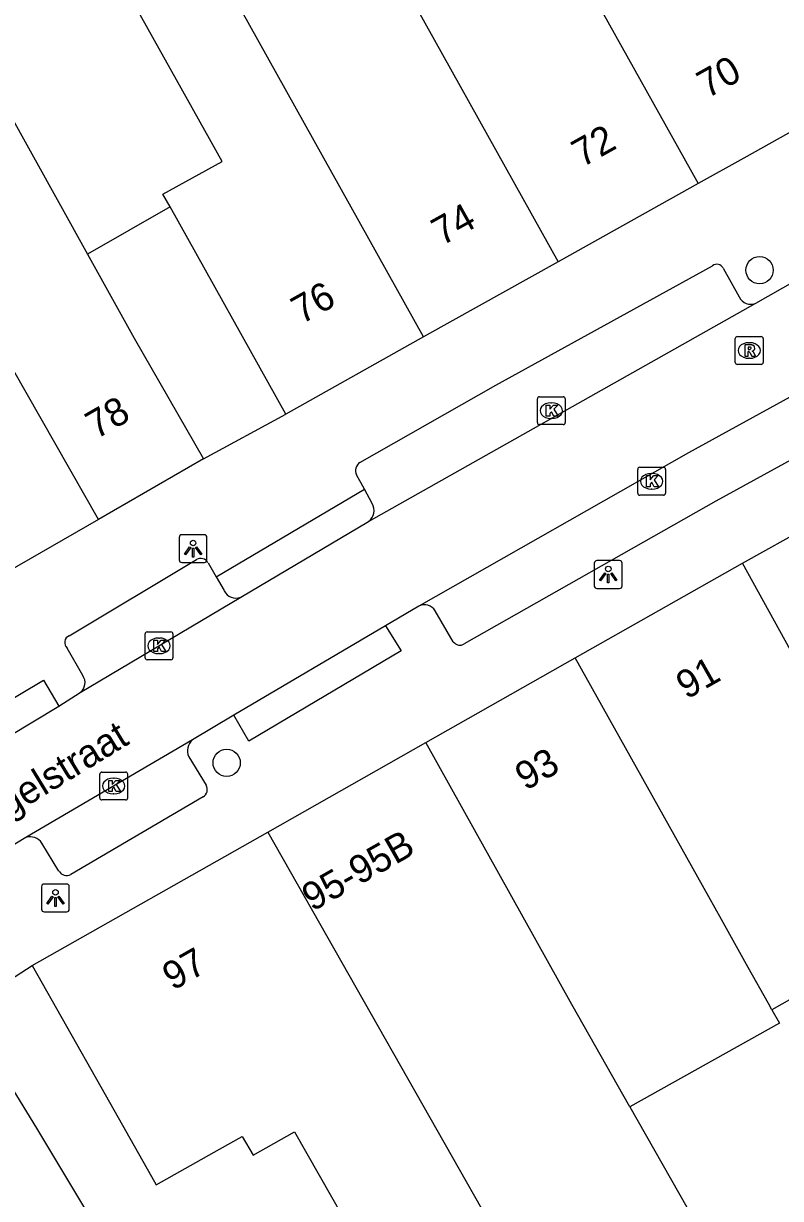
# Model space of a CAD drawing. Extents: x 159718 to 160783, y 383290 to 384030.
# Drawn here: x 160474.17 to 160501.32, y 383362.07 to 383404.19 of the extents above; entities that cross this region are included whole.
import ezdxf

# ---------------------------------------------------------------- set-up
doc = ezdxf.new("R2010")
doc.units = 0
for name, color, linetype in [('IMGEO_Boom', 7, 'Continuous'), ('IMGEO_Kolk', 7, 'Continuous'), ('IMGEO_Lichtpunt', 7, 'Continuous'), ('IMGEO_Openbare_ruimte_label', 7, 'Continuous'), ('IMGEO_Pand', 7, 'Continuous'), ('IMGEO_Pand_nummerreeks', 7, 'Continuous'), ('IMGEO_Pand_overbouw', 7, 'Continuous'), ('IMGEO_Rijbaan_lokaal_open', 7, 'Continuous'), ('IMGEO_Rioolput', 7, 'Continuous'), ('IMGEO_Voetpad_open', 7, 'Continuous')]:
    doc.layers.add(name, color=color, linetype=linetype)

msp = doc.modelspace()

# ---------------------------------------------------------------- linework, layer by layer
at = {"layer": 'IMGEO_Boom'}
for centre in [(160500.57, 383395.347), (160481.459, 383377.686)]:
    msp.add_circle(centre, 0.489, dxfattribs=at)
at = {"layer": 'IMGEO_Kolk'}
for p, q in [((160492.6, 383389.884), (160492.6, 383390.736)), ((160492.675, 383390.81), (160493.527, 383390.81)), ((160493.601, 383390.736), (160493.601, 383389.884)), ((160493.088, 383390.59), (160493.113, 383390.59)), ((160493.527, 383389.81), (160492.675, 383389.81)), ((160493.111, 383390.03), (160493.086, 383390.03)), ((160496.197, 383387.355), (160496.197, 383388.207)), ((160496.272, 383388.281), (160497.124, 383388.281)), ((160497.198, 383388.207), (160497.198, 383387.355)), ((160496.685, 383388.061), (160496.71, 383388.061)), ((160497.124, 383387.281), (160496.272, 383387.281)), ((160496.708, 383387.501), (160496.683, 383387.501)), ((160478.532, 383381.454), (160478.532, 383382.306)), ((160478.607, 383382.38), (160479.459, 383382.38)), ((160479.533, 383382.306), (160479.533, 383381.454)), ((160479.02, 383382.16), (160479.045, 383382.16)), ((160479.459, 383381.38), (160478.607, 383381.38)), ((160479.043, 383381.6), (160479.018, 383381.6)), ((160476.908, 383376.428), (160476.908, 383377.28)), ((160476.983, 383377.354), (160477.835, 383377.354)), ((160477.396, 383377.134), (160477.421, 383377.134)), ((160477.909, 383377.28), (160477.909, 383376.428)), ((160477.835, 383376.354), (160476.983, 383376.354)), ((160477.419, 383376.574), (160477.394, 383376.574))]:
    msp.add_line(p, q, dxfattribs=at)
for points in [[(160492.6, 383389.884), (160492.6, 383390.736)], [(160492.675, 383390.81), (160493.527, 383390.81)], [(160493.601, 383390.736), (160493.601, 383389.884)], [(160492.921, 383390.51), (160493.044, 383390.51), (160493.044, 383390.359), (160493.174, 383390.51), (160493.338, 383390.51), (160493.192, 383390.359), (160493.345, 383390.11), (160493.193, 383390.11), (160493.108, 383390.274), (160493.044, 383390.207), (160493.044, 383390.11), (160492.921, 383390.11), (160492.921, 383390.51)], [(160493.527, 383389.81), (160492.675, 383389.81)], [(160496.197, 383387.355), (160496.197, 383388.207)], [(160496.272, 383388.281), (160497.124, 383388.281)], [(160497.198, 383388.207), (160497.198, 383387.355)], [(160496.518, 383387.981), (160496.641, 383387.981), (160496.641, 383387.83), (160496.771, 383387.981), (160496.935, 383387.981), (160496.789, 383387.83), (160496.942, 383387.581), (160496.79, 383387.581), (160496.705, 383387.745), (160496.641, 383387.678), (160496.641, 383387.581), (160496.518, 383387.581), (160496.518, 383387.981)], [(160497.124, 383387.281), (160496.272, 383387.281)], [(160478.532, 383381.454), (160478.532, 383382.306)], [(160478.607, 383382.38), (160479.459, 383382.38)], [(160479.533, 383382.306), (160479.533, 383381.454)], [(160478.853, 383382.08), (160478.976, 383382.08), (160478.976, 383381.929), (160479.106, 383382.08), (160479.27, 383382.08), (160479.124, 383381.929), (160479.277, 383381.68), (160479.125, 383381.68), (160479.04, 383381.844), (160478.976, 383381.777), (160478.976, 383381.68), (160478.853, 383381.68), (160478.853, 383382.08)], [(160479.459, 383381.38), (160478.607, 383381.38)], [(160476.908, 383376.428), (160476.908, 383377.28)], [(160476.983, 383377.354), (160477.835, 383377.354)], [(160477.909, 383377.28), (160477.909, 383376.428)], [(160477.229, 383377.054), (160477.352, 383377.054), (160477.352, 383376.903), (160477.482, 383377.054), (160477.646, 383377.054), (160477.5, 383376.903), (160477.653, 383376.654), (160477.501, 383376.654), (160477.416, 383376.818), (160477.352, 383376.751), (160477.352, 383376.654), (160477.229, 383376.654), (160477.229, 383377.054)], [(160477.835, 383376.354), (160476.983, 383376.354)]]:
    msp.add_lwpolyline(points, dxfattribs=at)
for centre, start, end in [((160492.677, 383390.734), 91.552, 178.448), ((160492.677, 383390.734), 91.552, 178.448), ((160493.525, 383390.734), 1.552, 88.448), ((160493.525, 383390.734), 1.552, 88.448), ((160492.677, 383389.886), 181.552, 268.448), ((160492.677, 383389.886), 181.552, 268.448), ((160493.525, 383389.886), 271.552, 358.448), ((160493.525, 383389.886), 271.552, 358.448), ((160496.274, 383388.205), 91.552, 178.448), ((160496.274, 383388.205), 91.552, 178.448), ((160497.122, 383388.205), 1.552, 88.448), ((160497.122, 383388.205), 1.552, 88.448), ((160496.274, 383387.357), 181.552, 268.448), ((160496.274, 383387.357), 181.552, 268.448), ((160497.122, 383387.357), 271.552, 358.448), ((160497.122, 383387.357), 271.552, 358.448), ((160478.609, 383382.304), 91.552, 178.448), ((160478.609, 383382.304), 91.552, 178.448), ((160479.457, 383382.304), 1.552, 88.448), ((160479.457, 383382.304), 1.552, 88.448), ((160478.609, 383381.456), 181.552, 268.448), ((160478.609, 383381.456), 181.552, 268.448), ((160479.457, 383381.456), 271.552, 358.448), ((160479.457, 383381.456), 271.552, 358.448), ((160476.985, 383377.278), 91.552, 178.448), ((160476.985, 383377.278), 91.552, 178.448), ((160477.833, 383377.278), 1.552, 88.448), ((160477.833, 383377.278), 1.552, 88.448), ((160476.985, 383376.43), 181.552, 268.448), ((160476.985, 383376.43), 181.552, 268.448), ((160477.833, 383376.43), 271.552, 358.448), ((160477.833, 383376.43), 271.552, 358.448)]:
    msp.add_arc(centre, 0.0765, start, end, dxfattribs=at)
for centre, major_axis, ratio, start_param, end_param in [((160493.087, 383390.31), (-0.387, 0.002), 0.722429, 4.712389, 7.853982), ((160493.112, 383390.31), (-0.39, 0.002), 0.717154, 1.570796, 4.712389), ((160496.684, 383387.781), (-0.387, 0.002), 0.722429, 4.712389, 7.853982), ((160496.709, 383387.781), (-0.39, 0.002), 0.717154, 1.570796, 4.712389), ((160479.019, 383381.88), (-0.387, 0.002), 0.722429, 4.712389, 7.853982), ((160479.044, 383381.88), (-0.39, 0.002), 0.717154, 1.570796, 4.712389), ((160477.395, 383376.854), (-0.387, 0.002), 0.722429, 4.712389, 7.853982), ((160477.42, 383376.854), (-0.39, 0.002), 0.717154, 1.570796, 4.712389)]:
    msp.add_ellipse(centre, major_axis=major_axis, ratio=ratio, start_param=start_param, end_param=end_param, dxfattribs=at)
at = {"layer": 'IMGEO_Lichtpunt'}
for p, q in [((160479.757, 383385.768), (160479.757, 383384.961)), ((160479.757, 383385.768), (160479.757, 383384.961)), ((160480.659, 383385.863), (160479.851, 383385.863)), ((160480.659, 383385.863), (160479.851, 383385.863)), ((160480.753, 383384.961), (160480.753, 383385.768)), ((160480.753, 383384.961), (160480.753, 383385.768)), ((160479.851, 383384.867), (160480.659, 383384.867)), ((160479.851, 383384.867), (160480.659, 383384.867)), ((160494.643, 383384.839), (160494.643, 383384.032)), ((160494.643, 383384.839), (160494.643, 383384.032)), ((160495.545, 383384.934), (160494.737, 383384.934)), ((160495.545, 383384.934), (160494.737, 383384.934)), ((160495.639, 383384.032), (160495.639, 383384.839)), ((160495.639, 383384.032), (160495.639, 383384.839)), ((160494.737, 383383.938), (160495.545, 383383.938)), ((160494.737, 383383.938), (160495.545, 383383.938)), ((160475.723, 383373.34), (160474.915, 383373.34)), ((160475.723, 383373.34), (160474.915, 383373.34)), ((160474.821, 383373.245), (160474.821, 383372.438)), ((160474.821, 383373.245), (160474.821, 383372.438)), ((160475.817, 383372.438), (160475.817, 383373.245)), ((160475.817, 383372.438), (160475.817, 383373.245)), ((160474.915, 383372.344), (160475.723, 383372.344)), ((160474.915, 383372.344), (160475.723, 383372.344))]:
    msp.add_line(p, q, dxfattribs=at)
for points in [[(160480.131, 383385.432), (160480.17, 383385.404), (160479.982, 383385.142), (160479.944, 383385.169), (160480.131, 383385.432)], [(160480.233, 383385.384), (160480.28, 383385.384), (160480.28, 383385.062), (160480.233, 383385.062), (160480.233, 383385.384)], [(160480.343, 383385.404), (160480.381, 383385.431), (160480.568, 383385.169), (160480.529, 383385.141), (160480.343, 383385.404)], [(160495.017, 383384.503), (160495.056, 383384.475), (160494.868, 383384.213), (160494.83, 383384.24), (160495.017, 383384.503)], [(160495.119, 383384.455), (160495.166, 383384.455), (160495.166, 383384.133), (160495.119, 383384.133), (160495.119, 383384.455)], [(160495.229, 383384.475), (160495.267, 383384.502), (160495.454, 383384.24), (160495.415, 383384.212), (160495.229, 383384.475)], [(160475.195, 383372.909), (160475.234, 383372.881), (160475.046, 383372.619), (160475.008, 383372.646), (160475.195, 383372.909)], [(160475.407, 383372.881), (160475.445, 383372.908), (160475.632, 383372.646), (160475.593, 383372.618), (160475.407, 383372.881)], [(160475.297, 383372.861), (160475.344, 383372.861), (160475.344, 383372.539), (160475.297, 383372.539), (160475.297, 383372.861)]]:
    msp.add_lwpolyline(points, dxfattribs=at)
for centre in [(160480.256, 383385.566), (160495.142, 383384.637), (160475.32, 383373.043)]:
    msp.add_circle(centre, 0.0994, dxfattribs=at)
for centre, start, end in [((160479.851, 383385.768), 90, 180), ((160479.851, 383385.768), 90, 180), ((160480.659, 383385.768), 0, 90), ((160480.659, 383385.768), 0, 90), ((160479.851, 383384.961), 180, 270), ((160479.851, 383384.961), 180, 270), ((160480.659, 383384.961), 270, 0), ((160480.659, 383384.961), 270, 360), ((160494.737, 383384.839), 90, 180), ((160494.737, 383384.839), 90, 180), ((160495.545, 383384.839), 0, 90), ((160495.545, 383384.839), 0, 90), ((160494.737, 383384.032), 180, 270), ((160494.737, 383384.032), 180, 270), ((160495.545, 383384.032), 270, 0), ((160495.545, 383384.032), 270, 360), ((160474.915, 383373.245), 90, 180), ((160474.915, 383373.245), 90, 180), ((160475.723, 383373.245), 0, 90), ((160475.723, 383373.245), 0, 90), ((160474.915, 383372.438), 180, 270), ((160474.915, 383372.438), 180, 270), ((160475.723, 383372.438), 270, 0), ((160475.723, 383372.438), 270, 360)]:
    msp.add_arc(centre, 0.0946, start, end, dxfattribs=at)
at = {"layer": 'IMGEO_Pand'}
for points in [[(160483.576, 383390.191), (160479.428, 383397.615), (160479.174, 383398.069), (160481.294, 383399.245), (160476.163, 383408.441), (160479.001, 383410.024)], [(160488.523, 383392.955), (160479.001, 383410.024)], [(160491.733, 383410.343), (160492.53, 383408.915), (160493.994, 383406.29), (160498.365, 383398.454)], [(160486.659, 383407.637), (160493.351, 383395.653)], [(160468.633, 383400.841), (160470.138, 383401.679), (160472.525, 383403.008), (160476.473, 383395.916), (160478.141, 383392.915), (160480.633, 383388.58)], [(160503.208, 383401.16), (160500, 383399.368), (160498.365, 383398.454)], [(160476.865, 383386.414), (160468.633, 383400.841)], [(160498.365, 383398.454), (160493.351, 383395.653)], [(160493.351, 383395.653), (160488.523, 383392.955)], [(160488.523, 383392.955), (160483.576, 383390.191)], [(160499.951, 383384.846), (160502.36, 383386.185), (160502.304, 383386.297), (160508.086, 383389.549)], [(160480.633, 383388.58), (160476.865, 383386.414)], [(160476.865, 383386.414), (160469.81, 383382.357)], [(160493.953, 383381.448), (160499.951, 383384.846)], [(160506.411, 383371.894), (160505.555, 383373.403), (160506.097, 383373.71), (160505.947, 383373.998), (160499.951, 383384.846)], [(160488.601, 383378.414), (160493.953, 383381.448)], [(160501.011, 383368.832), (160500.886, 383369.055), (160500.164, 383370.345), (160499.197, 383372.073), (160498.744, 383372.883), (160493.953, 383381.448)], [(160482.934, 383375.203), (160488.601, 383378.414)], [(160495.919, 383365.354), (160493.834, 383369.027), (160488.601, 383378.414)], [(160474.49, 383370.418), (160482.934, 383375.203)], [(160482.934, 383375.203), (160491.645, 383359.858), (160492.727, 383357.952)], [(160506.411, 383371.894), (160501.011, 383368.832)], [(160474.49, 383370.418), (160476.949, 383366.065), (160478.765, 383362.85), (160478.932, 383362.554), (160481.205, 383363.833), (160482.02, 383364.291), (160482.405, 383363.614), (160483.893, 383364.459), (160486.934, 383359.106), (160486.44, 383358.826)], [(160472.243, 383354.191), (160478.604, 383358.023), (160476.988, 383360.706), (160474.653, 383364.584), (160472.034, 383368.843)], [(160501.011, 383368.832), (160501.279, 383368.353), (160495.919, 383365.354)], [(160495.919, 383365.354), (160500, 383358.164), (160500.229, 383357.761), (160500.597, 383357.113), (160504.871, 383359.614), (160506.61, 383356.155), (160506.076, 383351.936), (160510.595, 383351.363)]]:
    msp.add_lwpolyline(points, dxfattribs=at)
at = {"layer": 'IMGEO_Pand_overbouw'}
msp.add_lwpolyline([(160479.428, 383397.615), (160476.473, 383395.916), (160478.141, 383392.915), (160480.633, 383388.58), (160483.576, 383390.191)], close=True, dxfattribs=at)
at = {"layer": 'IMGEO_Rijbaan_lokaal_open'}
for points in [[(160509.795, 383395.27), (160498.016, 383388.805), (160488.35, 383383.3)], [(160500.433, 383394.16), (160501.848, 383394.965)], [(160486.541, 383386.343), (160500.433, 383394.16)], [(160481.968, 383383.62), (160486.541, 383386.343)], [(160476.209, 383380.206), (160481.968, 383383.62)], [(160488.35, 383383.3), (160487.16, 383382.594)], [(160487.16, 383382.594), (160481.715, 383379.396)], [(160475.436, 383379.714), (160476.209, 383380.206)], [(160471.815, 383377.547), (160475.436, 383379.714)], [(160481.715, 383379.396), (160480.24, 383378.511)], [(160480.24, 383378.511), (160474.257, 383375.009)], [(160474.257, 383375.009), (160473.53, 383374.563)]]:
    msp.add_lwpolyline(points, dxfattribs=at)
at = {"layer": 'IMGEO_Rioolput'}
for p, q in [((160499.697, 383392.042), (160499.697, 383392.894)), ((160499.772, 383392.968), (160500.624, 383392.968)), ((160500.185, 383392.748), (160500.21, 383392.748)), ((160500.698, 383392.894), (160500.698, 383392.042)), ((160500.624, 383391.968), (160499.772, 383391.968)), ((160500.208, 383392.188), (160500.183, 383392.188))]:
    msp.add_line(p, q, dxfattribs=at)
for points in [[(160499.697, 383392.042), (160499.697, 383392.894)], [(160499.772, 383392.968), (160500.624, 383392.968)], [(160500.698, 383392.894), (160500.698, 383392.042)], [(160500.286, 383392.666), (160500.034, 383392.668), (160500.034, 383392.268)], [(160500.034, 383392.268), (160500.158, 383392.268), (160500.158, 383392.43), (160500.169, 383392.43)], [(160500.212, 383392.587), (160500.158, 383392.587), (160500.158, 383392.506)], [(160500.158, 383392.506), (160500.21, 383392.506)], [(160500.216, 383392.401), (160500.287, 383392.268), (160500.427, 383392.268), (160500.362, 383392.394)], [(160500.624, 383391.968), (160499.772, 383391.968)]]:
    msp.add_lwpolyline(points, dxfattribs=at)
for centre, radius, start, end in [((160499.774, 383392.892), 0.0765, 91.552, 178.448), ((160499.774, 383392.892), 0.0765, 91.552, 178.448), ((160500.622, 383392.892), 0.0765, 1.552, 88.448), ((160500.622, 383392.892), 0.0765, 1.552, 88.448), ((160500.168, 383392.377), 0.0533, 26.0293, 88.6989), ((160500.194, 383392.695), 0.19, 274.7715, 282.9687), ((160500.218, 383392.491), 0.0964, 77.0061, 93.1865), ((160500.232, 383392.548), 0.0378, 276.6634, 79.6772), ((160500.285, 383392.556), 0.109, 350.3612, 89.416), ((160500.283, 383392.556), 0.112, 277.5842, 350.9817), ((160500.267, 383392.341), 0.108, 29.5134, 73.7905), ((160499.774, 383392.044), 0.0765, 181.552, 268.448), ((160499.774, 383392.044), 0.0765, 181.552, 268.448), ((160500.622, 383392.044), 0.0765, 271.552, 358.448), ((160500.622, 383392.044), 0.0765, 271.552, 358.448)]:
    msp.add_arc(centre, radius, start, end, dxfattribs=at)
for centre, major_axis, ratio, start_param, end_param in [((160500.184, 383392.468), (-0.387, 0.002), 0.722429, 4.712389, 7.853982), ((160500.209, 383392.468), (-0.39, 0.002), 0.717154, 1.570796, 4.712389)]:
    msp.add_ellipse(centre, major_axis=major_axis, ratio=ratio, start_param=start_param, end_param=end_param, dxfattribs=at)
at = {"layer": 'IMGEO_Voetpad_open'}
for points in [[(160486.238, 383388.451), (160491.109, 383391.228), (160498.885, 383395.508)], [(160499.261, 383395.426), (160499.838, 383394.391)], [(160510.062, 383393.132), (160498.996, 383387.068), (160489.978, 383381.951)], [(160480.633, 383388.58), (160483.576, 383390.191)], [(160486.396, 383387.493), (160486.116, 383388.013)], [(160481.085, 383384.359), (160486.396, 383387.493)], [(160486.679, 383386.98), (160486.396, 383387.493)], [(160475.812, 383382.242), (160480.378, 383384.971)], [(160480.79, 383384.858), (160481.085, 383384.359)], [(160481.085, 383384.359), (160481.364, 383383.858)], [(160489.586, 383382.025), (160488.935, 383383.129)], [(160487.16, 383382.594), (160487.721, 383381.698), (160482.26, 383378.462), (160481.715, 383379.396)], [(160476.3, 383380.814), (160475.742, 383381.8)], [(160471.815, 383377.547), (160471.256, 383378.484), (160474.889, 383380.65), (160475.436, 383379.714)], [(160480.099, 383377.899), (160480.719, 383376.881)], [(160480.614, 383376.466), (160475.866, 383373.682)], [(160475.447, 383373.797), (160474.833, 383374.807)], [(160472.034, 383368.843), (160474.49, 383370.418)]]:
    msp.add_lwpolyline(points, dxfattribs=at)
for centre, radius, start, end in [((160499.037, 383395.302), 0.256, 28.9902, 126.4043), ((160500.255, 383394.583), 0.459, 204.7135, 292.8506), ((160486.413, 383388.166), 0.334, 121.5508, 207.3201), ((160486.267, 383386.736), 0.479, 304.8927, 30.66), ((160480.532, 383384.725), 0.29, 27.2076, 122.1175), ((160481.797, 383384.07), 0.482, 206.1507, 290.8365), ((160488.555, 383382.916), 0.436, 29.3002, 118.1117), ((160475.918, 383381.999), 0.266, 113.6084, 228.3931), ((160489.82, 383382.188), 0.285, 214.9121, 303.7074), ((160475.931, 383380.558), 0.449, 308.2444, 34.7309), ((160480.585, 383378.109), 0.53, 130.6737, 203.3781), ((160480.471, 383376.723), 0.294, 299.1539, 32.449), ((160474.412, 383374.529), 0.504, 33.4488, 107.9002), ((160475.724, 383373.984), 0.334, 214.0225, 295.2823)]:
    msp.add_arc(centre, radius, start, end, dxfattribs=at)

# ---------------------------------------------------------------- texts
at = {"layer": 'IMGEO_Openbare_ruimte_label'}
msp.add_text('Gagelstraat', height=1, rotation=31.3372, dxfattribs=at).set_placement((160472.111, 383374.79))
at = {"layer": 'IMGEO_Pand_nummerreeks'}
for s, rotation, p in [('70', 29.1922, (160498.692, 383401.488)), ('72', 29.1922, (160494.203, 383399.016)), ('74', 29.1948, (160489.174, 383396.206)), ('76', 29.1948, (160484.142, 383393.395)), ('78', 29.8969, (160476.78, 383389.271)), ('91', 29.5302, (160497.948, 383379.941)), ('93', 29.5417, (160492.176, 383376.67)), ('95-95B', 29.536, (160484.531, 383372.338)), ('97', 29.5417, (160479.528, 383369.503))]:
    msp.add_text(s, height=1, rotation=rotation, dxfattribs=at).set_placement(p)

doc.saveas('drawing.dxf')
